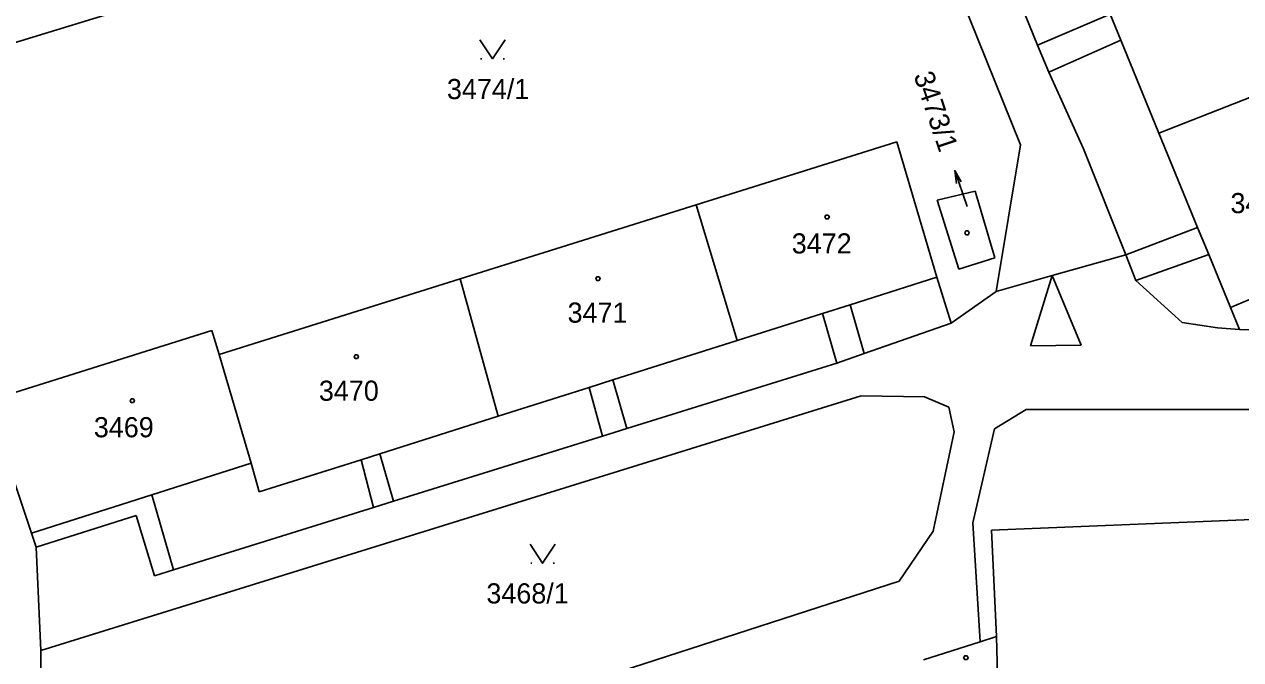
# Model space of a CAD drawing. Extents: x -263587 to -261993, y -1238795 to -1236748.
# Drawn here: x -262868.2 to -262771.6, y -1238497 to -1238446.6 of the extents above; entities that cross this region are included whole.
import ezdxf

# ---------------------------------------------------------------- set-up
doc = ezdxf.new("R2010")
doc.units = 0
doc.layers.add('Vrstva 1', color=7, linetype='Continuous')

msp = doc.modelspace()

# ---------------------------------------------------------------- linework, layer by layer
at = {"layer": 'Vrstva 1'}
for p, q in [((-262789.05, -1238456.12), (-262800.89, -1238426.81)), ((-262800.89, -1238426.81), (-262789.05, -1238456.12)), ((-262793.58, -1238433.92), (-262787.7, -1238448.2)), ((-262787.7, -1238448.2), (-262793.58, -1238433.92)), ((-262841.06, -1238439.47), (-262873.85, -1238449.49)), ((-262873.85, -1238449.49), (-262841.06, -1238439.47)), ((-262787.7, -1238448.2), (-262781.94, -1238445.73)), ((-262781.94, -1238445.73), (-262781.08, -1238447.82)), ((-262781.08, -1238447.82), (-262781.94, -1238445.73)), ((-262786.81, -1238450.35), (-262781.08, -1238447.82)), ((-262781.08, -1238447.82), (-262778.06, -1238455.2)), ((-262778.06, -1238455.2), (-262781.08, -1238447.82)), ((-262787.7, -1238448.2), (-262786.81, -1238450.35)), ((-262786.81, -1238450.35), (-262787.7, -1238448.2)), ((-262831.96, -1238449.29), (-262831.86, -1238449.29)), ((-262830.16, -1238449.29), (-262830.06, -1238449.29)), ((-262786.81, -1238450.35), (-262784.06, -1238456.43)), ((-262784.06, -1238456.43), (-262786.81, -1238450.35)), ((-262778.06, -1238455.2), (-262767.41, -1238451.02)), ((-262767.41, -1238451.02), (-262778.06, -1238455.2)), ((-262778.06, -1238455.2), (-262774.99, -1238462.69)), ((-262774.99, -1238462.69), (-262778.06, -1238455.2)), ((-262798.88, -1238455.89), (-262814.84, -1238460.9)), ((-262814.84, -1238460.9), (-262798.88, -1238455.89)), ((-262795.7, -1238466.64), (-262798.88, -1238455.89)), ((-262798.88, -1238455.89), (-262795.7, -1238466.64)), ((-262791, -1238467.76), (-262789.05, -1238456.12)), ((-262789.05, -1238456.12), (-262791, -1238467.76)), ((-262784.06, -1238456.43), (-262780.7, -1238464.86)), ((-262780.7, -1238464.86), (-262784.06, -1238456.43)), ((-262794.149, -1238459.184), (-262794.285, -1238458.173)), ((-262792.67, -1238459.81), (-262795.68, -1238460.51)), ((-262795.68, -1238460.51), (-262792.67, -1238459.81)), ((-262791.11, -1238465.11), (-262792.67, -1238459.81)), ((-262792.67, -1238459.81), (-262791.11, -1238465.11)), ((-262814.84, -1238460.9), (-262833.57, -1238466.77)), ((-262833.57, -1238466.77), (-262814.84, -1238460.9)), ((-262811.58, -1238471.67), (-262814.84, -1238460.9)), ((-262814.84, -1238460.9), (-262811.58, -1238471.67)), ((-262795.68, -1238460.51), (-262793.97, -1238466)), ((-262793.97, -1238466), (-262795.68, -1238460.51)), ((-262780.7, -1238464.86), (-262774.99, -1238462.69)), ((-262774.99, -1238462.69), (-262774.1, -1238464.84)), ((-262774.1, -1238464.84), (-262774.99, -1238462.69)), ((-262793.97, -1238466), (-262791.11, -1238465.11)), ((-262791.11, -1238465.11), (-262793.97, -1238466)), ((-262780.7, -1238464.86), (-262786.55, -1238466.5)), ((-262786.55, -1238466.5), (-262780.7, -1238464.86)), ((-262779.9, -1238466.91), (-262780.7, -1238464.86)), ((-262780.7, -1238464.86), (-262779.9, -1238466.91)), ((-262779.9, -1238466.91), (-262774.1, -1238464.84)), ((-262774.1, -1238464.84), (-262772.39, -1238469.03)), ((-262772.39, -1238469.03), (-262774.1, -1238464.84)), ((-262761.87, -1238464.6), (-262772.39, -1238469.03)), ((-262772.39, -1238469.03), (-262761.87, -1238464.6)), ((-262833.57, -1238466.77), (-262852.74, -1238472.78)), ((-262852.74, -1238472.78), (-262833.57, -1238466.77)), ((-262830.55, -1238477.68), (-262833.57, -1238466.77)), ((-262833.57, -1238466.77), (-262830.55, -1238477.68)), ((-262802.6, -1238468.83), (-262795.7, -1238466.64)), ((-262795.7, -1238466.64), (-262802.6, -1238468.83)), ((-262795.7, -1238466.64), (-262794.56, -1238470.28)), ((-262786.55, -1238466.5), (-262791, -1238467.76)), ((-262791, -1238467.76), (-262786.55, -1238466.5)), ((-262788.26, -1238472.09), (-262786.55, -1238466.5)), ((-262786.55, -1238466.5), (-262784.23, -1238472.04)), ((-262776.21, -1238470.23), (-262779.9, -1238466.91)), ((-262779.9, -1238466.91), (-262776.21, -1238470.23)), ((-262791, -1238467.76), (-262794.56, -1238470.28)), ((-262794.56, -1238470.28), (-262791, -1238467.76)), ((-262804.79, -1238469.52), (-262802.6, -1238468.83)), ((-262802.6, -1238468.83), (-262804.79, -1238469.52)), ((-262801.49, -1238472.7), (-262802.6, -1238468.83)), ((-262772.39, -1238469.03), (-262771.66, -1238470.79)), ((-262771.66, -1238470.79), (-262772.39, -1238469.03)), ((-262811.58, -1238471.67), (-262804.79, -1238469.52)), ((-262804.79, -1238469.52), (-262811.58, -1238471.67)), ((-262804.79, -1238469.52), (-262803.65, -1238473.46)), ((-262853.31, -1238470.87), (-262871.16, -1238476.48)), ((-262871.16, -1238476.48), (-262853.31, -1238470.87)), ((-262852.74, -1238472.78), (-262853.31, -1238470.87)), ((-262853.31, -1238470.87), (-262852.74, -1238472.78)), ((-262794.56, -1238470.28), (-262801.49, -1238472.7)), ((-262801.49, -1238472.7), (-262794.56, -1238470.28)), ((-262773.42, -1238470.67), (-262776.21, -1238470.23)), ((-262776.21, -1238470.23), (-262773.42, -1238470.67)), ((-262771.66, -1238470.79), (-262773.42, -1238470.67)), ((-262773.42, -1238470.67), (-262771.66, -1238470.79)), ((-262739.16, -1238472.01), (-262771.66, -1238470.79)), ((-262771.66, -1238470.79), (-262739.16, -1238472.01)), ((-262821.46, -1238474.8), (-262811.58, -1238471.67)), ((-262811.58, -1238471.67), (-262821.46, -1238474.8)), ((-262850.19, -1238481.41), (-262852.74, -1238472.78)), ((-262852.74, -1238472.78), (-262850.19, -1238481.41)), ((-262801.49, -1238472.7), (-262803.65, -1238473.46)), ((-262803.65, -1238473.46), (-262801.49, -1238472.7)), ((-262784.23, -1238472.04), (-262788.26, -1238472.09)), ((-262803.65, -1238473.46), (-262820.33, -1238478.65)), ((-262820.33, -1238478.65), (-262803.65, -1238473.46)), ((-262823.33, -1238475.39), (-262821.46, -1238474.8)), ((-262821.46, -1238474.8), (-262823.33, -1238475.39)), ((-262821.46, -1238474.8), (-262820.33, -1238478.65)), ((-262830.55, -1238477.68), (-262823.33, -1238475.39)), ((-262823.33, -1238475.39), (-262830.55, -1238477.68)), ((-262823.33, -1238475.39), (-262822.28, -1238479.26)), ((-262871.16, -1238476.48), (-262867.65, -1238486.97)), ((-262867.65, -1238486.97), (-262871.16, -1238476.48)), ((-262866.91, -1238496.29), (-262801.73, -1238476.05)), ((-262801.73, -1238476.05), (-262866.91, -1238496.29)), ((-262801.73, -1238476.05), (-262796.69, -1238476.13)), ((-262796.69, -1238476.13), (-262801.73, -1238476.05)), ((-262796.69, -1238476.13), (-262794.75, -1238476.95)), ((-262794.75, -1238476.95), (-262796.69, -1238476.13)), ((-262839.96, -1238480.66), (-262830.55, -1238477.68)), ((-262830.55, -1238477.68), (-262839.96, -1238480.66)), ((-262794.75, -1238476.95), (-262794.34, -1238478.93)), ((-262794.34, -1238478.93), (-262794.75, -1238476.95)), ((-262791.12, -1238478.68), (-262788.6, -1238477.15)), ((-262788.6, -1238477.15), (-262791.12, -1238478.68)), ((-262788.6, -1238477.15), (-262761.74, -1238477.14)), ((-262761.74, -1238477.14), (-262788.6, -1238477.15)), ((-262820.33, -1238478.65), (-262822.28, -1238479.26)), ((-262822.28, -1238479.26), (-262820.33, -1238478.65)), ((-262792.85, -1238486.14), (-262791.12, -1238478.68)), ((-262791.12, -1238478.68), (-262792.85, -1238486.14)), ((-262822.28, -1238479.26), (-262838.88, -1238484.43)), ((-262838.88, -1238484.43), (-262822.28, -1238479.26)), ((-262794.34, -1238478.93), (-262796.01, -1238486.8)), ((-262796.01, -1238486.8), (-262794.34, -1238478.93)), ((-262841.46, -1238481.13), (-262839.96, -1238480.66)), ((-262839.96, -1238480.66), (-262841.46, -1238481.13)), ((-262839.96, -1238480.66), (-262838.88, -1238484.43)), ((-262858.08, -1238483.92), (-262850.19, -1238481.41)), ((-262850.19, -1238481.41), (-262858.08, -1238483.92)), ((-262850.19, -1238481.41), (-262849.54, -1238483.69)), ((-262849.54, -1238483.69), (-262850.19, -1238481.41)), ((-262849.54, -1238483.69), (-262841.46, -1238481.13)), ((-262841.46, -1238481.13), (-262849.54, -1238483.69)), ((-262841.46, -1238481.13), (-262840.47, -1238484.93)), ((-262867.65, -1238486.97), (-262858.08, -1238483.92)), ((-262858.08, -1238483.92), (-262867.65, -1238486.97)), ((-262858.08, -1238483.92), (-262856.37, -1238489.88)), ((-262838.88, -1238484.43), (-262840.47, -1238484.93)), ((-262840.47, -1238484.93), (-262838.88, -1238484.43)), ((-262840.47, -1238484.93), (-262856.37, -1238489.88)), ((-262856.37, -1238489.88), (-262840.47, -1238484.93)), ((-262739.57, -1238484.61), (-262791.38, -1238486.73)), ((-262791.38, -1238486.73), (-262739.57, -1238484.61)), ((-262859.32, -1238485.56), (-262867.28, -1238488.07)), ((-262867.28, -1238488.07), (-262859.32, -1238485.56)), ((-262857.86, -1238490.35), (-262859.32, -1238485.56)), ((-262859.32, -1238485.56), (-262857.86, -1238490.35)), ((-262792.28, -1238495.59), (-262792.85, -1238486.14)), ((-262792.85, -1238486.14), (-262792.28, -1238495.59)), ((-262867.65, -1238486.97), (-262867.28, -1238488.07)), ((-262867.28, -1238488.07), (-262867.65, -1238486.97)), ((-262796.01, -1238486.8), (-262798.71, -1238490.79)), ((-262798.71, -1238490.79), (-262796.01, -1238486.8)), ((-262791.38, -1238486.73), (-262790.97, -1238495.17)), ((-262790.97, -1238495.17), (-262791.38, -1238486.73)), ((-262867.28, -1238488.07), (-262866.91, -1238496.29)), ((-262866.91, -1238496.29), (-262867.28, -1238488.07)), ((-262827.98, -1238489.35), (-262827.88, -1238489.35)), ((-262826.18, -1238489.35), (-262826.08, -1238489.35)), ((-262856.37, -1238489.88), (-262857.86, -1238490.35)), ((-262857.86, -1238490.35), (-262856.37, -1238489.88)), ((-262798.71, -1238490.79), (-262822.66, -1238498.53)), ((-262822.66, -1238498.53), (-262798.71, -1238490.79)), ((-262790.97, -1238495.17), (-262792.28, -1238495.59)), ((-262792.28, -1238495.59), (-262790.97, -1238495.17)), ((-262790.77, -1238502.37), (-262790.97, -1238495.17)), ((-262790.97, -1238495.17), (-262790.77, -1238502.37)), ((-262796.77, -1238497.02), (-262792.28, -1238495.59)), ((-262792.28, -1238495.59), (-262796.77, -1238497.02)), ((-262866.91, -1238496.29), (-262866.54, -1238519.8)), ((-262866.54, -1238519.8), (-262866.91, -1238496.29))]:
    msp.add_line(p, q, dxfattribs=at)
for points in [[(-262832.01, -1238447.79), (-262831.01, -1238449.29), (-262830.01, -1238447.79)], [(-262793.31, -1238461.01), (-262794.285, -1238458.173), (-262793.771, -1238459.054)], [(-262828.03, -1238487.85), (-262827.03, -1238489.35), (-262826.03, -1238487.85)]]:
    msp.add_lwpolyline(points, dxfattribs=at)
for points in [[(-262804.34, -1238461.7), (-262804.25, -1238461.85), (-262804.34, -1238462), (-262804.52, -1238462), (-262804.61, -1238461.85), (-262804.52, -1238461.7)], [(-262793.22, -1238462.96), (-262793.13, -1238463.11), (-262793.22, -1238463.26), (-262793.4, -1238463.26), (-262793.49, -1238463.11), (-262793.4, -1238462.96)], [(-262822.54, -1238466.6), (-262822.45, -1238466.75), (-262822.54, -1238466.9), (-262822.72, -1238466.9), (-262822.81, -1238466.75), (-262822.72, -1238466.6)], [(-262841.74, -1238472.8), (-262841.65, -1238472.95), (-262841.74, -1238473.1), (-262841.92, -1238473.1), (-262842.01, -1238472.95), (-262841.92, -1238472.8)], [(-262859.54, -1238476.3), (-262859.45, -1238476.45), (-262859.54, -1238476.6), (-262859.72, -1238476.6), (-262859.81, -1238476.45), (-262859.72, -1238476.3)], [(-262793.31, -1238496.71), (-262793.22, -1238496.86), (-262793.31, -1238497.01), (-262793.49, -1238497.01), (-262793.58, -1238496.86), (-262793.49, -1238496.71)]]:
    msp.add_lwpolyline(points, close=True, dxfattribs=at)

# ---------------------------------------------------------------- texts
msp.add_text('3473/1', height=1.6, rotation=288.42695, dxfattribs=at).set_placement((-262797.568, -1238450.593))
for s, p in [('3474/1', (-262834.634, -1238452.49)), ('3467', (-262772.382, -1238461.55)), ('3472', (-262807.238, -1238464.75)), ('3471', (-262825.049, -1238470.25)), ('3470', (-262844.807, -1238476.45)), ('3469', (-262862.688, -1238479.35)), ('3468/1', (-262831.498, -1238492.55))]:
    msp.add_text(s, height=1.6, dxfattribs=at).set_placement(p)

doc.saveas('drawing.dxf')
